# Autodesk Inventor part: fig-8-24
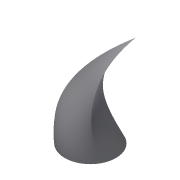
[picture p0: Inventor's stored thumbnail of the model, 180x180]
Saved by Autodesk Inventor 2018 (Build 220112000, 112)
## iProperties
Shininess: 77.0
Angle Display Precision: 2
Document Length Units: 11269
Document Angle Units: 11279
Document Time Units: 11290
Document Mass Units: 11283
Document Length Units Precision: 3
Document Angle Units Precision: 2
Created: 2001-12
Part Number: fig-8-24
Document SubType Name: Modeling
Designer: CADSoft
Density: 1 g/cm^3
Material: Generic
Appearance: Default
Density: 0.0
Volumn: 0.0
Area: 0.0
PropertySet Name: Model Information
Control State: 0
Master: False
Checked Out: False
Author: CADSoft
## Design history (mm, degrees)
workplane "Work Plane3"
workplane "Work Plane4"
sketch "Sketch12"
  geometry: L1 (0, 10.598)-(9.178, -5.299); L2 (9.178, -5.299)-(-9.178, -5.299); L3 (-9.178, -5.299)-(0, 10.598); 1 further point
  constraints: 6 end point, 5 other
workplane "Work Plane5"
loft "Loft5" dims "d57" = 0, "d58" = 90 deg, "d59" = 0, "d60" = 90 deg, "d61" = 0, "d62" = 90 deg
body "Solid1"
sketch "Sketch1"
  geometry: C1 r 19.387 at (0, 0); 1 further point
  constraints: 1 centre point, 1 coincident, 1 other
sketch "Sketch2"
  geometry: 1 further point
